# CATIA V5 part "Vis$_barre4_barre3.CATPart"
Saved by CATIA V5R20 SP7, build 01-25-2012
Part number: Vis_barre4_barre3
Bounding box of the stored display mesh (mm): x -2.5 to 6.5, y 2.165 to 4.165, z 5.188 to 7.187
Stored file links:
  J:\IFMA\IAO\système avant mef\Vis$_barre4_barre3.CATPart
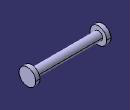
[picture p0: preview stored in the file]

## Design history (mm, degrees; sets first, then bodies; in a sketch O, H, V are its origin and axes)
Body1 (main body)
  Line1 "barre4": stored without definition
  Point1 "Point_D_vis": stored without definition
  Plane1: type Normal, Curve Line1, RefPoint Point1
  Line2 "barre_3": stored without definition
  Line3 "axe_liaison_barre3_barre4": stored without definition
  DatumCurve1
  Line4 "axe_liaison_barre3_barre4": stored without definition
  DatumCurve2
  Line5: stored without definition
  DatumCurve3
  Line6 "axe_liaison_barre3_barre4": stored without definition
  Sketch1 on Plane1, origin (0, 3.1651, 6.1875), H (-1, 0, 0), V (0, -0.8903, 0.4554)
    point P1 (2.5, 0)
    line L1 (2.5, 0) -> (2.5, 1)
    line L2 (2.5, 1) -> (2, 1)
    line L3 (2, 1) -> (2, 0.5)
    line L4 (2, 0.5) -> (-6, 0.5)
    line L5 (-6, 0.5) -> (-6, 1)
    line L6 (-6, 1) -> (-6.5, 1)
    line L7 (-6.5, 1) -> (-6.5, 0)
    point P8 (-6.5, 0)
    reference projected line E1 (-6, -14.4582) -> (-6, 0) from Line2
    reference projected line E2 (0, 0) -> (-20, 0) from Line3
    reference projected line E3 (-6, -14.0264) -> (-6, 0.4318) from edge of DatumCurve1
    reference projected line E4 (0, 0) -> (-20, 0) from Line4
    reference projected line E5 (2, -1) -> (2, 1) from edge of DatumCurve2
    reference projected line E6 (4, 0) -> (-2, 0) from Line5
    reference projected line E7 (2, -1) -> (2, 1) from edge of DatumCurve3
    distance L6 E2 = 1
    distance L7 E3 = 0.5
    distance L4 E4 = 0.5
    distance L2 E6 = 1
    distance L1 E7 = 0.5
    coincidence: P1 H, P8 H, L5 E1, E5 L3
    vertical: L1 V, L3 V, L5 V, L7 V
    horizontal: L2 H, L4 H, L6 H
  Shaft1: profile Sketch1, axis Line6, angle 360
